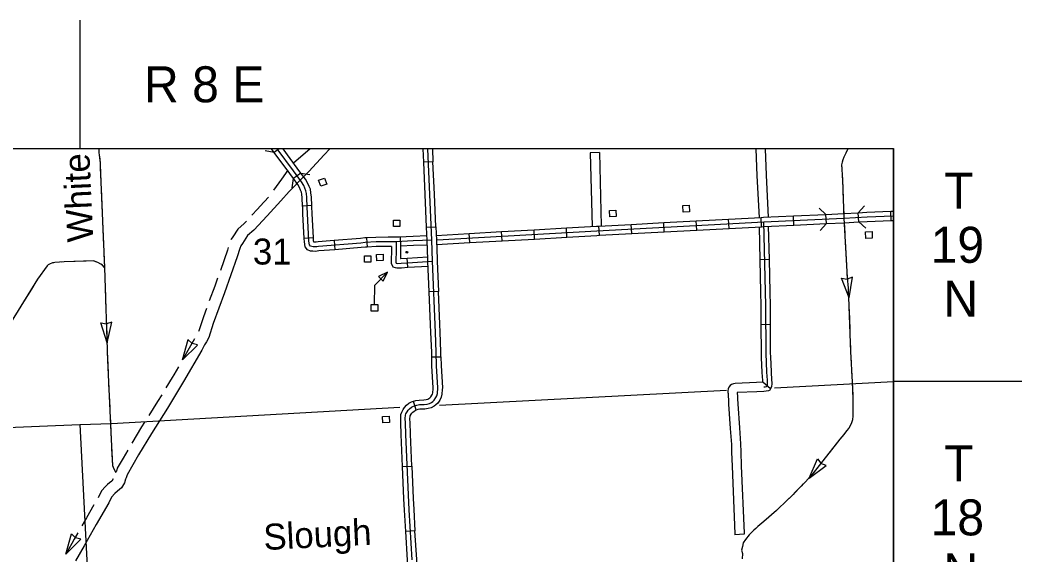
# Model space of a CAD drawing. Extents: x -0.3 to 2.65, y 0 to 1.9.
# Drawn here: x 0.8619 to 1.0569, y 0.4627 to 0.5667 of the extents above; entities that cross this region are included whole.
import ezdxf

# ---------------------------------------------------------------- set-up
doc = ezdxf.new("R2010")
doc.units = 0
for name, color, linetype in [('DSN_DRFT_DNC', 7, 'Continuous'), ('Level 11', 7, 'Continuous'), ('Level 12', 7, 'Continuous'), ('Level 13', 7, 'Continuous'), ('Level 14', 7, 'Continuous'), ('Level 15', 7, 'Continuous'), ('Level 17', 7, 'Continuous'), ('Level 18', 7, 'Continuous'), ('Level 19', 7, 'Continuous'), ('Level 20', 7, 'Continuous'), ('Level 29', 7, 'Continuous'), ('Level 6', 7, 'Continuous'), ('SHET_Annotations', 7, 'Continuous')]:
    doc.layers.add(name, color=color, linetype=linetype)

msp = doc.modelspace()

# ---------------------------------------------------------------- linework, layer by layer
at = {"layer": 'DSN_DRFT_DNC'}
msp.add_lwpolyline([(0.38477, 0.54167), (1.0319, 0.54167), (1.0319, 0.1443), (0.38477, 0.1443)], close=True, dxfattribs=at)
at = {"layer": 'Level 11'}
msp.add_line((1.00873, 0.49517), (1.03189, 0.4964), dxfattribs=at)
for points in [[(0.94356, 0.49181), (0.99941, 0.49467)], [(0.87975, 0.48824), (0.93585, 0.49141)], [(0.81668, 0.4859), (0.85625, 0.4873), (0.87357, 0.48799)], [(0.87357, 0.48799), (0.87975, 0.48824)], [(0.87357, 0.48799), (0.87673, 0.42636)]]:
    msp.add_lwpolyline(points, dxfattribs=at)
at = {"layer": 'Level 12'}
for p, q in [((0.91839, 0.54164), (0.91518, 0.53881)), ((1.02392, 0.51668), (1.0229, 0.51629)), ((1.02329, 0.51262), (1.02392, 0.51668)), ((1.02329, 0.51262), (1.0218, 0.51645)), ((1.0218, 0.51645), (1.02288, 0.51629)), ((0.87887, 0.50389), (0.87768, 0.50782)), ((0.87768, 0.50782), (0.87875, 0.50757)), ((0.87981, 0.50789), (0.87876, 0.50757)), ((0.87887, 0.50389), (0.87981, 0.50789)), ((0.89356, 0.50059), (0.89464, 0.50455)), ((0.89356, 0.50059), (0.89647, 0.50348)), ((0.89462, 0.50454), (0.89541, 0.50378)), ((0.89648, 0.5035), (0.89542, 0.50377)), ((1.01547, 0.47758), (1.01709, 0.48135)), ((1.01547, 0.47758), (1.01876, 0.48004)), ((1.01709, 0.48135), (1.01775, 0.48048)), ((1.01876, 0.48004), (1.01776, 0.48047)), ((0.87087, 0.4628), (0.87194, 0.46677)), ((0.87194, 0.46677), (0.87272, 0.46599)), ((0.87378, 0.4657), (0.87273, 0.46598)), ((0.87087, 0.4628), (0.87378, 0.4657))]:
    msp.add_line(p, q, dxfattribs=at)
for points in [[(0.9222, 0.54164), (0.92109, 0.54048), (0.91811, 0.53723), (0.91703, 0.53609), (0.9143, 0.53335), (0.91269, 0.5315), (0.91002, 0.5286), (0.90745, 0.5258), (0.90622, 0.52476), (0.90522, 0.52324), (0.90493, 0.52278), (0.90471, 0.52227), (0.9042, 0.52062), (0.90173, 0.51365), (0.89951, 0.50766), (0.89865, 0.50495), (0.89822, 0.50411), (0.89786, 0.50349), (0.8973, 0.50248), (0.89375, 0.49637), (0.89062, 0.49121), (0.8875, 0.48629), (0.88499, 0.48212), (0.88388, 0.4802), (0.88277, 0.47823), (0.88259, 0.47766), (0.88249, 0.47739), (0.88225, 0.47669), (0.88169, 0.47573), (0.88128, 0.47539), (0.88089, 0.47509), (0.88042, 0.4746), (0.87976, 0.47388), (0.8792, 0.47279), (0.87675, 0.4686), (0.87439, 0.46445), (0.87276, 0.46151)], [(0.87726, 0.54164), (0.87729, 0.54089), (0.87755, 0.53886), (0.87758, 0.53663), (0.8784, 0.51858), (0.87898, 0.50054), (0.87967, 0.48512), (0.87991, 0.48005), (0.8802, 0.47941), (0.88059, 0.47866)], [(0.87738, 0.54018), (0.87755, 0.53886), (0.87756, 0.53783)], [(1.02299, 0.54164), (1.02261, 0.5408), (1.02226, 0.54001), (1.02204, 0.53946), (1.02191, 0.539), (1.0218, 0.5385), (1.02184, 0.53767), (1.0219, 0.53649), (1.02195, 0.53565), (1.02225, 0.52815), (1.02285, 0.51662), (1.02309, 0.5145), (1.02354, 0.50218), (1.02386, 0.49632), (1.02397, 0.49298), (1.02396, 0.49201), (1.02398, 0.49061), (1.02398, 0.48972), (1.02392, 0.48891), (1.02364, 0.48814), (1.02321, 0.48734), (1.02273, 0.48677), (1.02221, 0.4861), (1.02146, 0.48519), (1.01601, 0.47826), (1.0147, 0.47684), (1.0139, 0.47601), (1.01237, 0.47444), (1.01064, 0.47273), (1.00976, 0.47194), (1.00913, 0.4713), (1.00666, 0.46917), (1.0055, 0.46816), (1.0047, 0.46745), (1.00382, 0.46655), (1.00308, 0.46565), (1.00266, 0.46498), (1.00249, 0.46429), (1.00234, 0.46361), (1.0025, 0.46291), (1.00244, 0.46192)], [(1.02299, 0.54164), (1.02261, 0.5408), (1.02226, 0.54001), (1.02204, 0.53946), (1.02191, 0.539), (1.0218, 0.5385), (1.02183, 0.53785)], [(0.87756, 0.53783), (0.87758, 0.53663), (0.87764, 0.53546)], [(0.91405, 0.53748), (0.91283, 0.53575), (0.91126, 0.53361)], [(1.02191, 0.53627), (1.02195, 0.53565), (1.02211, 0.53154)], [(0.87771, 0.53388), (0.87792, 0.52915)], [(0.91027, 0.5322), (0.90866, 0.53046)], [(0.90866, 0.53046), (0.90812, 0.52988), (0.90706, 0.52872)], [(1.02218, 0.52996), (1.02221, 0.52904)], [(0.878, 0.52757), (0.87821, 0.52283)], [(0.90599, 0.52755), (0.90555, 0.52708), (0.90432, 0.52603), (0.90332, 0.52452), (0.90303, 0.52405), (0.90299, 0.52395)], [(1.0223, 0.52725), (1.0224, 0.52523)], [(0.90247, 0.52246), (0.9023, 0.52189), (0.90092, 0.51798)], [(1.02249, 0.52365), (1.02273, 0.51892)], [(0.87828, 0.52126), (0.8784, 0.51858), (0.87847, 0.51652)], [(0.8784, 0.51858), (0.87798, 0.51903), (0.87764, 0.51918), (0.87709, 0.51955), (0.87618, 0.51984), (0.87051, 0.51964), (0.8687, 0.51952), (0.86828, 0.51945), (0.86766, 0.51919), (0.86742, 0.51906), (0.86722, 0.51889), (0.86537, 0.51631), (0.85366, 0.4975)], [(0.86853, 0.51949), (0.86828, 0.51945), (0.86766, 0.51919), (0.86742, 0.51906), (0.86722, 0.51889), (0.86537, 0.51631), (0.86532, 0.51622)], [(0.87484, 0.51979), (0.87051, 0.51964), (0.8701, 0.51961)], [(0.8784, 0.51858), (0.87798, 0.51903), (0.87764, 0.51918), (0.87709, 0.51955), (0.87641, 0.51977)], [(1.02282, 0.51734), (1.02285, 0.51662), (1.02309, 0.5145), (1.02316, 0.51261)], [(0.86448, 0.51488), (0.86198, 0.51086)], [(0.87852, 0.51494), (0.87867, 0.51021)], [(0.90039, 0.51649), (0.89984, 0.51493), (0.89876, 0.51204)], [(1.02321, 0.51104), (1.0233, 0.50867)], [(0.89821, 0.51056), (0.89761, 0.50894), (0.89675, 0.50623), (0.89668, 0.50608)], [(0.87872, 0.50863), (0.87887, 0.50389)], [(1.0233, 0.50867), (1.02339, 0.5063)], [(0.89592, 0.50469), (0.8954, 0.50375), (0.89356, 0.50059)], [(1.02345, 0.50472), (1.02354, 0.50218), (1.02366, 0.49999)], [(0.87892, 0.50231), (0.87898, 0.50054), (0.879, 0.49995)], [(0.879, 0.49995), (0.87911, 0.49758)], [(0.89277, 0.49922), (0.89186, 0.49765), (0.89157, 0.49718)], [(0.89157, 0.49718), (0.89034, 0.49515)], [(1.02375, 0.49841), (1.02386, 0.49632), (1.02395, 0.49368)], [(0.87918, 0.496), (0.87939, 0.49127)], [(0.88952, 0.4938), (0.88872, 0.49249), (0.88701, 0.48978)], [(1.02396, 0.4921), (1.02396, 0.49201), (1.02398, 0.49061), (1.02398, 0.48972), (1.02392, 0.48891), (1.02364, 0.48814), (1.0233, 0.4875)], [(0.87946, 0.48969), (0.87967, 0.48512), (0.87967, 0.48496)], [(0.88616, 0.48845), (0.8856, 0.48757), (0.8837, 0.4844)], [(1.02233, 0.48625), (1.02221, 0.4861), (1.02146, 0.48519), (1.01938, 0.48254)], [(0.87975, 0.48338), (0.87991, 0.48005), (0.8802, 0.47941), (0.88053, 0.47879)], [(0.88289, 0.48305), (0.88199, 0.48148), (0.88087, 0.47951), (0.8807, 0.47894), (0.88067, 0.47887)], [(1.0184, 0.4813), (1.01601, 0.47826), (1.01542, 0.47762)], [(0.88005, 0.47743), (0.87979, 0.477), (0.87938, 0.47666), (0.87899, 0.47637), (0.87852, 0.47588), (0.87786, 0.47516), (0.8773, 0.47407), (0.87713, 0.47378)], [(1.01434, 0.47647), (1.0139, 0.47601), (1.01269, 0.47477)], [(1.01269, 0.47477), (1.01237, 0.47444), (1.01101, 0.4731)], [(0.87633, 0.47241), (0.87485, 0.46987), (0.87396, 0.46831)], [(1.00985, 0.47203), (1.00976, 0.47194), (1.00913, 0.4713), (1.00666, 0.46917), (1.00632, 0.46887)], [(0.87318, 0.46694), (0.87249, 0.46572), (0.87202, 0.46487)], [(1.00513, 0.46783), (1.0047, 0.46745), (1.00382, 0.46655), (1.00308, 0.46565), (1.00266, 0.46498), (1.00249, 0.46429), (1.00243, 0.46406)], [(0.87202, 0.46487), (0.87087, 0.4628)]]:
    msp.add_lwpolyline(points, dxfattribs=at)
at = {"layer": 'Level 13'}
for p, q in [((1.00774, 0.52009), (1.00594, 0.52005)), ((1.00797, 0.50744), (1.00617, 0.50743)), ((1.00799, 0.49494), (1.00647, 0.49625))]:
    msp.add_line(p, q, dxfattribs=at)
for points in [[(1.00594, 0.52005), (1.00579, 0.52647)], [(1.00664, 0.49536), (1.00693, 0.49537), (1.00716, 0.49541), (1.00728, 0.49551), (1.00736, 0.49565), (1.00739, 0.49596), (1.00738, 0.49611), (1.00735, 0.49661), (1.00725, 0.49821), (1.0071, 0.50191), (1.00706, 0.51117), (1.00667, 0.52741)], [(1.00774, 0.52009), (1.00758, 0.52656)], [(1.0061, 0.51373), (1.00594, 0.52005)], [(1.00789, 0.51378), (1.00774, 0.52009)], [(1.00617, 0.50743), (1.00616, 0.51116), (1.0061, 0.51373)], [(1.00797, 0.50744), (1.00795, 0.51118), (1.00789, 0.51378)], [(1.00623, 0.50108), (1.0062, 0.50189), (1.00617, 0.50743)], [(1.00803, 0.50116), (1.00799, 0.50193), (1.00797, 0.50744)], [(1.00647, 0.49625), (1.00645, 0.49655), (1.00636, 0.49816), (1.00623, 0.50108)], [(1.00799, 0.49494), (1.00823, 0.49539), (1.00829, 0.49595), (1.00827, 0.49617), (1.00824, 0.49666), (1.00815, 0.49825), (1.00803, 0.50116)]]:
    msp.add_lwpolyline(points, dxfattribs=at)
at = {"layer": 'Level 15'}
for p, q in [((0.9114, 0.54094), (0.91089, 0.54164)), ((0.91236, 0.54164), (0.9114, 0.54094)), ((0.91658, 0.53691), (0.91514, 0.53584)), ((0.91872, 0.53061), (0.91693, 0.5305)), ((1.01252, 0.52679), (1.01244, 0.52858)), ((1.01883, 0.52709), (1.01875, 0.52888)), ((1.02515, 0.52742), (1.02504, 0.52921)), ((1.03144, 0.52768), (1.03138, 0.52948)), ((0.97467, 0.52481), (0.97457, 0.5266)), ((0.98098, 0.52514), (0.98088, 0.52694)), ((0.98729, 0.52548), (0.98719, 0.52727)), ((0.9936, 0.52582), (0.9935, 0.52761)), ((0.99991, 0.52615), (0.99981, 0.52795)), ((1.00621, 0.52649), (1.00612, 0.52828)), ((0.9359, 0.52446), (0.936, 0.52267)), ((0.94944, 0.52338), (0.94934, 0.52517)), ((0.95575, 0.52373), (0.95565, 0.52553)), ((0.96206, 0.52409), (0.96195, 0.52588)), ((0.96836, 0.52445), (0.96826, 0.52624)), ((0.91903, 0.52429), (0.91723, 0.52419)), ((0.92306, 0.52379), (0.9232, 0.522)), ((0.92938, 0.52431), (0.92948, 0.52252)), ((0.93738, 0.51859), (0.93724, 0.52038))]:
    msp.add_line(p, q, dxfattribs=at)
for points in [[(0.91514, 0.53584), (0.91441, 0.53683), (0.9114, 0.54094)], [(0.94205, 0.52386), (0.93846, 0.52371), (0.93511, 0.52352), (0.93356, 0.52355), (0.93121, 0.52351), (0.92911, 0.5234), (0.92825, 0.5233), (0.92001, 0.52265), (0.91966, 0.5226), (0.91933, 0.52259), (0.91895, 0.52259), (0.91869, 0.52261), (0.91844, 0.52271), (0.91827, 0.52295), (0.91816, 0.52364), (0.91788, 0.52903), (0.91784, 0.53031), (0.91773, 0.53218), (0.91766, 0.53293), (0.91756, 0.53349), (0.91736, 0.53396), (0.91713, 0.53448), (0.91672, 0.53521), (0.91513, 0.53736), (0.912, 0.54164)], [(0.91658, 0.53691), (0.91585, 0.53789), (0.91311, 0.54164)], [(0.91872, 0.53061), (0.91863, 0.53225), (0.91855, 0.53304), (0.91843, 0.53375), (0.91818, 0.53431), (0.91794, 0.53488), (0.91747, 0.5357), (0.91658, 0.53691)], [(0.91693, 0.5305), (0.91684, 0.53211), (0.91677, 0.53281), (0.9167, 0.53323), (0.91653, 0.5336), (0.91633, 0.53408), (0.91597, 0.53472), (0.91514, 0.53584)], [(0.91723, 0.52419), (0.91698, 0.529), (0.91695, 0.53027), (0.91693, 0.5305)], [(0.91903, 0.52429), (0.91878, 0.52907), (0.91874, 0.53035), (0.91872, 0.53061)], [(0.94308, 0.52391), (0.97416, 0.52568), (1.00667, 0.52741), (1.02225, 0.52815), (1.02674, 0.52841), (1.03178, 0.52859), (1.03189, 0.5286)], [(1.00612, 0.52828), (1.00662, 0.52831), (1.01244, 0.52858)], [(1.01244, 0.52858), (1.01875, 0.52888)], [(1.01875, 0.52888), (1.0222, 0.52904), (1.02504, 0.52921)], [(1.02504, 0.52921), (1.02669, 0.52931), (1.03138, 0.52948)], [(1.03138, 0.52948), (1.03175, 0.52949), (1.03189, 0.52949)], [(0.96826, 0.52624), (0.97411, 0.52657), (0.97457, 0.5266)], [(0.97457, 0.5266), (0.98088, 0.52694)], [(0.98088, 0.52694), (0.98719, 0.52727)], [(0.98719, 0.52727), (0.9935, 0.52761)], [(0.9935, 0.52761), (0.99981, 0.52795)], [(0.99981, 0.52795), (1.00612, 0.52828)], [(0.99991, 0.52615), (1.00621, 0.52649)], [(1.00621, 0.52649), (1.00671, 0.52652), (1.01252, 0.52679)], [(1.01252, 0.52679), (1.01883, 0.52709)], [(1.01883, 0.52709), (1.0223, 0.52725), (1.02515, 0.52742)], [(1.02515, 0.52742), (1.02678, 0.52752), (1.03144, 0.52768)], [(1.03144, 0.52768), (1.03181, 0.5277), (1.03189, 0.5277)], [(0.93569, 0.52445), (0.93509, 0.52442), (0.93357, 0.52444), (0.93117, 0.52441), (0.92938, 0.52431)], [(0.94112, 0.52472), (0.93841, 0.52461), (0.93569, 0.52445)], [(0.94291, 0.5248), (0.94934, 0.52517)], [(0.94934, 0.52517), (0.95565, 0.52553)], [(0.95565, 0.52553), (0.96195, 0.52588)], [(0.96195, 0.52588), (0.96826, 0.52624)], [(0.96206, 0.52409), (0.96836, 0.52445)], [(0.96836, 0.52445), (0.9742, 0.52478), (0.97467, 0.52481)], [(0.97467, 0.52481), (0.98098, 0.52514)], [(0.98098, 0.52514), (0.98729, 0.52548)], [(0.98729, 0.52548), (0.9936, 0.52582)], [(0.9936, 0.52582), (0.99991, 0.52615)], [(0.9232, 0.522), (0.92011, 0.52176), (0.91973, 0.52171), (0.91935, 0.52169), (0.91891, 0.5217), (0.91849, 0.52173), (0.91786, 0.52197), (0.91742, 0.5226), (0.91727, 0.52355), (0.91723, 0.52419)], [(0.92306, 0.52379), (0.91992, 0.52354), (0.91958, 0.5235), (0.91932, 0.52349), (0.91909, 0.52349), (0.91905, 0.52374), (0.91903, 0.52429)], [(0.92938, 0.52431), (0.92904, 0.52429), (0.92816, 0.5242), (0.92306, 0.52379)], [(0.92948, 0.52252), (0.92918, 0.5225), (0.92833, 0.52241), (0.9232, 0.522)], [(0.93421, 0.52264), (0.93356, 0.52265), (0.93124, 0.52261), (0.92948, 0.52252)], [(0.93421, 0.52264), (0.9342, 0.52184), (0.93415, 0.51988), (0.93413, 0.51939), (0.93449, 0.5187), (0.93495, 0.51853), (0.93527, 0.51846), (0.93615, 0.51849), (0.93738, 0.51859)], [(0.93511, 0.52352), (0.9351, 0.52182), (0.93504, 0.51985), (0.93503, 0.5196), (0.93513, 0.51942), (0.9352, 0.51939), (0.93534, 0.51936), (0.9361, 0.51939), (0.93734, 0.51948), (0.94221, 0.51977)], [(0.936, 0.52267), (0.936, 0.52181), (0.93595, 0.52028), (0.93605, 0.52029), (0.93724, 0.52038)], [(0.94119, 0.52292), (0.9385, 0.52282), (0.936, 0.52267)], [(0.94298, 0.52301), (0.94944, 0.52338)], [(0.94944, 0.52338), (0.95575, 0.52373)], [(0.95575, 0.52373), (0.96206, 0.52409)], [(0.93724, 0.52038), (0.93728, 0.52038), (0.94128, 0.52062)], [(0.93738, 0.51859), (0.9374, 0.51859), (0.94135, 0.51882)]]:
    msp.add_lwpolyline(points, dxfattribs=at)
at = {"layer": 'Level 17'}
for points in [[(0.97469, 0.54092), (0.9729, 0.54087), (0.97324, 0.52652)], [(0.97469, 0.54092), (0.97503, 0.52662)], [(1.00509, 0.54164), (1.00533, 0.5364), (1.00573, 0.52826)], [(1.00689, 0.54164), (1.00712, 0.53648), (1.00752, 0.52835)], [(1.00647, 0.49625), (1.00521, 0.49619), (1.00111, 0.49601), (1.00073, 0.49595), (1.00035, 0.49577), (1.0001, 0.49559), (0.99984, 0.49528), (0.99972, 0.49494), (0.99967, 0.49456), (0.99969, 0.49427), (0.99971, 0.49402), (0.99973, 0.49344), (0.99978, 0.49289), (0.99982, 0.49197), (1.00012, 0.48723), (1.00035, 0.48415), (1.00038, 0.48264), (1.00047, 0.47994), (1.00102, 0.46675), (1.00104, 0.46656)], [(1.00799, 0.49494), (1.00781, 0.49472), (1.0076, 0.49456), (1.00668, 0.49446), (1.00529, 0.4944), (1.00149, 0.49423), (1.0015, 0.49413), (1.00152, 0.49356), (1.00157, 0.49302), (1.00162, 0.49207), (1.00191, 0.48735), (1.00214, 0.48424), (1.00218, 0.48269), (1.00226, 0.48001), (1.00282, 0.46687), (1.00283, 0.46671), (1.00104, 0.46656)]]:
    msp.add_lwpolyline(points, dxfattribs=at)
at = {"layer": 'Level 18'}
for p, q in [((0.94049, 0.53904), (0.94038, 0.54164)), ((0.94217, 0.54164), (0.94228, 0.53912)), ((0.94228, 0.53912), (0.94049, 0.53904)), ((0.94049, 0.53904), (0.94049, 0.53904)), ((0.94104, 0.52642), (0.94284, 0.52649)), ((0.94334, 0.51386), (0.94155, 0.51379)), ((0.94155, 0.51379), (0.94155, 0.51379)), ((0.94205, 0.50119), (0.94384, 0.50121)), ((0.93904, 0.49083), (0.93848, 0.49254)), ((0.93638, 0.47985), (0.93817, 0.47993)), ((0.93879, 0.46733), (0.937, 0.46722))]:
    msp.add_line(p, q, dxfattribs=at)
for points in [[(0.93822, 0.46171), (0.93764, 0.47143), (0.93701, 0.48609), (0.93693, 0.48833), (0.93691, 0.48917), (0.93695, 0.48981), (0.93704, 0.49008), (0.93726, 0.49049), (0.93747, 0.49079), (0.93774, 0.4911), (0.9381, 0.49138), (0.93848, 0.4916), (0.93915, 0.49181), (0.93965, 0.49188), (0.9406, 0.49191), (0.94114, 0.492), (0.94163, 0.49213), (0.94201, 0.49232), (0.94225, 0.49252), (0.94253, 0.49278), (0.94286, 0.49324), (0.94305, 0.49361), (0.94314, 0.49403), (0.94321, 0.49515), (0.94297, 0.49944), (0.94293, 0.50211), (0.94276, 0.50593), (0.94221, 0.51977), (0.94205, 0.52386), (0.94127, 0.54164)], [(0.94077, 0.53273), (0.94049, 0.53904)], [(0.94256, 0.53281), (0.94228, 0.53912)], [(0.94104, 0.52642), (0.94077, 0.53273)], [(0.94284, 0.52649), (0.94256, 0.53281)], [(0.9413, 0.52011), (0.94116, 0.52382), (0.94104, 0.52642)], [(0.94284, 0.52649), (0.94295, 0.52389), (0.94309, 0.52018)], [(0.94155, 0.51379), (0.94131, 0.51974), (0.9413, 0.52011)], [(0.94309, 0.52018), (0.94311, 0.51981), (0.94334, 0.51386)], [(0.9418, 0.50748), (0.94155, 0.51379)], [(0.9436, 0.50755), (0.94334, 0.51386)], [(0.94205, 0.50119), (0.94204, 0.50209), (0.94187, 0.50589), (0.9418, 0.50748)], [(0.94384, 0.50121), (0.94383, 0.50214), (0.94366, 0.50596), (0.9436, 0.50755)], [(0.9423, 0.49495), (0.94231, 0.49515), (0.94207, 0.49941), (0.94205, 0.50119)], [(0.94384, 0.50121), (0.94387, 0.49947), (0.94411, 0.49515), (0.94409, 0.49484)], [(0.93848, 0.49254), (0.93894, 0.49269), (0.93957, 0.49278), (0.94052, 0.49281), (0.94095, 0.49288), (0.94131, 0.49297), (0.94151, 0.49308), (0.94166, 0.4932), (0.94186, 0.49338), (0.94209, 0.49371), (0.9422, 0.49392), (0.94225, 0.49416), (0.9423, 0.49495)], [(0.94409, 0.49484), (0.94403, 0.49391), (0.9439, 0.49331), (0.94362, 0.49277), (0.94321, 0.49218), (0.94284, 0.49184), (0.94251, 0.49157), (0.94196, 0.49129), (0.94133, 0.49112), (0.94069, 0.49102), (0.93972, 0.49099), (0.93935, 0.49094), (0.93904, 0.49083)], [(0.93611, 0.48617), (0.93604, 0.4883), (0.93602, 0.48918), (0.93606, 0.48997), (0.9362, 0.49043), (0.93649, 0.49096), (0.93676, 0.49134), (0.93711, 0.49175), (0.9376, 0.49214), (0.93812, 0.49242), (0.93848, 0.49254)], [(0.9379, 0.48624), (0.93783, 0.48835), (0.93781, 0.48915), (0.93784, 0.48965), (0.93787, 0.48973), (0.93802, 0.49002), (0.93818, 0.49024), (0.93836, 0.49044), (0.9386, 0.49063), (0.93884, 0.49077), (0.93904, 0.49083)], [(0.93638, 0.47985), (0.93611, 0.48606), (0.93611, 0.48617)], [(0.93817, 0.47993), (0.93791, 0.48613), (0.9379, 0.48624)], [(0.93665, 0.47354), (0.93638, 0.47985)], [(0.93817, 0.47993), (0.93845, 0.47362)], [(0.937, 0.46722), (0.93675, 0.47139), (0.93665, 0.47354)], [(0.93845, 0.47362), (0.93854, 0.47148), (0.93879, 0.46733)], [(0.93736, 0.46092), (0.93733, 0.46167), (0.937, 0.46722)], [(0.93915, 0.46101), (0.93912, 0.46176), (0.93879, 0.46733)]]:
    msp.add_lwpolyline(points, dxfattribs=at)
at = {"layer": 'Level 19'}
for points in [[(0.92121, 0.53595), (0.92163, 0.53478), (0.92045, 0.53435), (0.92003, 0.53552)], [(0.99096, 0.52934), (0.99091, 0.53058), (0.99216, 0.53064), (0.99221, 0.52939)], [(0.97668, 0.52838), (0.97661, 0.52962), (0.97786, 0.52969), (0.97793, 0.52844)], [(0.93459, 0.52654), (0.93459, 0.52778), (0.93584, 0.52778), (0.93584, 0.52654)], [(1.02652, 0.52422), (1.02646, 0.52546), (1.02771, 0.52552), (1.02776, 0.52428)], [(0.93022, 0.52084), (0.93023, 0.51959), (0.92898, 0.51958), (0.92897, 0.52083)], [(0.93258, 0.52112), (0.93259, 0.51988), (0.93134, 0.51987), (0.93133, 0.52111)], [(0.93169, 0.51677), (0.93257, 0.51592), (0.93341, 0.51765)], [(0.93029, 0.51008), (0.93029, 0.51133), (0.93154, 0.51133), (0.93154, 0.51008)], [(0.93256, 0.48832), (0.93249, 0.48956), (0.93374, 0.48964), (0.93381, 0.48839)]]:
    msp.add_lwpolyline(points, close=True, dxfattribs=at)
msp.add_lwpolyline([(0.93091, 0.51133), (0.93095, 0.51514), (0.93341, 0.51765)], dxfattribs=at)
msp.add_circle((0.93722, 0.52151), 0.000179, dxfattribs=at)
at = {"layer": 'Level 29'}
for points in [[(0.9114, 0.54094), (0.90963, 0.54122)], [(0.91658, 0.53691), (0.91836, 0.53664)], [(0.91487, 0.53407), (0.91514, 0.53584)], [(1.02504, 0.52921), (1.02624, 0.53055)], [(1.01742, 0.53009), (1.01875, 0.52888)], [(1.01883, 0.52709), (1.01762, 0.52576)], [(1.02649, 0.52623), (1.02515, 0.52742)]]:
    msp.add_lwpolyline(points, dxfattribs=at)
at = {"layer": 'Level 6'}
msp.add_line((1.03189, 0.14427), (1.03189, 0.54164), dxfattribs=at)
msp.add_lwpolyline([(1.03189, 0.54164), (1.03189, 0.54164), (0.38476, 0.54164)], dxfattribs=at)
at = {"layer": 'SHET_Annotations'}
for p, q in [((0.87357, 0.56667), (0.87357, 0.54167)), ((1.03189, 0.49646), (1.05689, 0.49646))]:
    msp.add_line(p, q, dxfattribs=at)

# ---------------------------------------------------------------- texts
at = {"layer": 'Level 12'}
msp.add_text('Slough', height=0.00505, rotation=2.8569, dxfattribs=at).set_placement((0.90943, 0.4636))
at = {"layer": 'Level 14'}
msp.add_text('White', height=0.00505, rotation=92.592, dxfattribs=at).set_placement((0.87621, 0.52361))
at = {"layer": 'Level 20'}
msp.add_text('31', height=0.00505, dxfattribs=at).set_placement((0.90725, 0.51913))
at = {"layer": 'SHET_Annotations'}
for s, p in [('R 8 E', (0.88607, 0.55067)), ('T', (1.04175, 0.52996)), ('19', (1.03911, 0.51946)), ('N', (1.04159, 0.50896)), ('T', (1.04175, 0.47696)), ('18', (1.0391, 0.46646)), ('N', (1.04159, 0.45596))]:
    msp.add_text(s, height=0.007, dxfattribs=at).set_placement(p)

doc.saveas('drawing.dxf')
